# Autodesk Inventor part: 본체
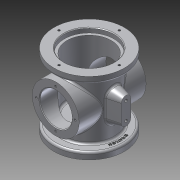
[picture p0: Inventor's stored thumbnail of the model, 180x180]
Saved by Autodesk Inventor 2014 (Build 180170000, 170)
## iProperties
Created: 2018-02
Part Number: 본체
Material: 알루미늄 6061
Document SubType Name: Modeling
Designer: OA65
Density: 2.71 g/cm^3
Appearance: 알루미늄 - 평지
Mass: 771.847 g
Surface Area: 821.675 cm^2
Volume: 284.814 cm^3
Author: OA65
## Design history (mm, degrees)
sketch "스케치1"
  geometry: C1 r 33 at (0, 0); C2 r 38 at (0, 0); 1 further point
  constraints: 2 centre point, 2 coincident
  dimensions: "d0" = 66 diameter of C1; "d1" = 76 diameter of C2
extrude "돌출1" new body sketch "스케치1" distance "d2" = 108; taper "d3" = 0 deg
sketch "스케치2"
  geometry: C1 r 38 at (0, 0) reference; C2 r 52.5 at (0, 0)
  constraints: 1 centre point, 1 coincident
  dimensions: "d4" = 105 diameter of C2
extrude "돌출2" join sketch "스케치2" distance "d5" = 10; taper "d6" = 0 deg
sketch "스케치3"
  geometry: C1 r 38 at (0, 0) reference; C2 r 52.5 at (0, 0)
  constraints: 1 centre point, 1 coincident
  dimensions: "d8" = 105 diameter of C2
extrude "돌출3" join sketch "스케치3" distance "d9" = 10; taper "d10" = 0 deg
sketch "스케치4"
  geometry: C1 r 52.5 at (0, 0) reference; C2 r 37 at (0, 0)
  constraints: 1 centre point, 1 coincident
  dimensions: "d11" = 74 diameter of C2
extrude "돌출4" cut sketch "스케치4" distance "d12" = 7; taper "d13" = 0 deg
sketch "스케치5"
  geometry: C1 r 37 at (0, 0) reference; C2 r 33 at (0, 0)
  constraints: 1 centre point, 1 coincident
  dimensions: "d14" = 66 diameter of C2
extrude "돌출5" cut sketch "스케치5" distance "d15" = 79; taper "d16" = 0 deg
sketch "스케치6"
  geometry: C1 r 52.5 at (0, 0) reference; C2 r 34 at (0, 0)
  constraints: 1 centre point, 1 coincident
  dimensions: "d17" = 68 diameter of C2
extrude "돌출6" cut sketch "스케치6" distance "d18" = 16; taper "d19" = 0 deg
sketch "스케치7"
  geometry: L1 (38, 10)-(52.5, 10) reference; L2 (52.5, 10)-(52.5, 0) reference; L3 (52.5, 0)-(37, 0) reference; L4 (37, 0)-(37, 7) reference; L5 (37, 7)-(33, 7) reference; L6 (33, 7)-(33, 86) reference; L7 (33, 86)-(-33, 86) reference; L8 (-33, 86)-(-33, 7) reference; L9 (-33, 7)-(-37, 7) reference; L10 (-37, 7)-(-37, 0) reference; L11 (-37, 0)-(-52.5, 0) reference; L12 (-52.5, 0)-(-52.5, 10) reference; L13 (-52.5, 10)-(-38, 10) reference; L14 (-38, 10)-(-38, 98) reference; L15 (-38, 98)-(-52.5, 98) reference; L16 (-52.5, 98)-(-52.5, 108) reference; L17 (-52.5, 108)-(-34, 108) reference; L18 (-34, 108)-(-34, 92) reference; L19 (-34, 92)-(34, 92) reference; L20 (34, 92)-(34, 108) reference; L21 (34, 108)-(52.5, 108) reference; L22 (52.5, 108)-(52.5, 98) reference; L23 (52.5, 98)-(38, 98) reference; L24 (38, 98)-(38, 10) reference; L25 (0, 108)-(0, 54); C1 r 24 at (0, 54); C2 r 35 at (0, 54); 1 further point
  constraints: 2 centre point, 2 coincident, 2 end point, 1 parallel
  dimensions: "d20" = 54 distance of L25.start L25.end; "d21" = 48 diameter of C1; "d22" = 70 diameter of C2
extrude "돌출7" join sketch "스케치7" stored distance "d23" = 100; taper "d24" = 0 deg
sketch "스케치8"
  geometry: C1 r 24 at (0, 0) reference; C2 r 35 at (0, 0) reference; C3 r 24 at (0, 0); 1 further point
  constraints: 1 centre point, 1 coincident, 1 concentric
extrude "돌출8" cut sketch "스케치8" distance "d25" = 150; taper "d26" = 0 deg
sketch "스케치9"
  geometry: C1 r 37 at (0, 0) reference; C2 r 52.5 at (0, 0) reference; C3 r 37 at (0, 0)
  constraints: 1 centre point, 1 coincident, 1 concentric
extrude "돌출9" cut sketch "스케치9" distance "d27" = 86; taper "d28" = 0 deg
sketch "스케치10"
  geometry: C1 r 37 at (0, 0) reference; C2 r 33 at (0, 0)
  constraints: 1 centre point, 1 coincident
  dimensions: "d29" = 66 diameter of C2
extrude "돌출10" join sketch "스케치10" distance "d30" = 79; taper "d31" = 0 deg
sketch "스케치11"
  geometry: C1 r 24 at (0, 0) reference; C2 r 35 at (0, 0) reference; C3 r 24 at (0, 0); 1 further point
  constraints: 1 centre point, 1 coincident, 1 concentric
extrude "돌출11" cut sketch "스케치11" distance "d32" = 150; taper "d33" = 0 deg
sketch "스케치12"
  geometry: C1 r 33 at (0, 0) reference; C2 r 5 at (0, 0)
  constraints: 1 centre point, 1 coincident
  dimensions: "d34" = 10 diameter of C2
extrude "돌출12" cut sketch "스케치12" distance "d35" = 14; taper "d36" = 0 deg
node "작업 평면1"
fillet "모깎기1" dims "d50" = 3
fillet "모깎기2" dims "d51" = 3
chamfer "모따기1" distance "d52" = 1; stored, may be unused: second distance "d53" = 2, angle "d54" = 45 deg
sketch "스케치17" dims "d64" = 90
  geometry: C1 r 38 at (0, 0) reference; 2 further points
  constraints: 1 coincident, 1 vertical alignment, 2 other
hole "구멍2" sketch "스케치17" at (0, 45) diameter "d65" = 3.242; stored, may be unused: countersink angle "d69" = 90 deg, drill point angle "d71" = 118 deg; dims "d66" = 4, "d67" = 4, "d68" = 2, "d70" = 6
sketch "스케치18" dims "d75" = 58
  geometry: C1 r 25 at (0, 0) reference; 3 further points
  constraints: 1 coincident, 1 vertical alignment, 2 other
hole "구멍3" sketch "스케치18" at (0, 29) diameter "d76" = 3.242; stored, may be unused: countersink angle "d80" = 90 deg, drill point angle "d82" = 118 deg; dims "d77" = 4, "d78" = 4, "d79" = 2, "d81" = 6
node "작업 평면2"
sketch "스케치19"
  geometry: L1 (-31, 92)-(-5, 92) reference; L2 (-5, 92)-(-5, 86) reference; L3 (-5, 86)-(-30, 86) reference; L4 (-33, 83)-(-33, 7) reference; L5 (-33, 7)-(-37, 7) reference; L6 (-37, 7)-(-37, 1) reference; L7 (-37, 1)-(-38, 0) reference; L8 (-38, 0)-(-43.379, 0) reference; L9 (-43.379, 0)-(-43.379, 6) reference; L10 (-43.379, 6)-(-45, 6.974) reference; L11 (-45, 6.974)-(-46.621, 6) reference; L12 (-46.621, 6)-(-46.621, 0) reference; L13 (-46.621, 0)-(-52.5, 0) reference; L14 (-52.5, 0)-(-52.5, 7) reference; L15 (-49.5, 10)-(-41, 10) reference; L16 (-38, 13)-(-38, 95) reference; L17 (-41, 98)-(-49.5, 98) reference; L18 (-52.5, 101)-(-52.5, 108) reference; L19 (-52.5, 108)-(-34, 108) reference; L20 (-34, 108)-(-34, 95) reference; L21 (34, 95)-(34, 108) reference; L22 (34, 108)-(52.5, 108) reference; L23 (52.5, 108)-(52.5, 101) reference; L24 (49.5, 98)-(41, 98) reference; L25 (38, 95)-(38, 13) reference; L26 (41, 10)-(49.5, 10) reference; L27 (52.5, 7)-(52.5, 0) reference; L28 (52.5, 0)-(46.621, 0) reference; L29 (46.621, 0)-(46.621, 6) reference; L30 (46.621, 6)-(45, 6.974) reference; L31 (45, 6.974)-(43.379, 6) reference; L32 (43.379, 6)-(43.379, 0) reference; L33 (43.379, 0)-(38, 0) reference; L34 (38, 0)-(37, 1) reference; L35 (37, 1)-(37, 7) reference; L36 (37, 7)-(33, 7) reference; L37 (33, 7)-(33, 83) reference; L38 (30, 86)-(5, 86) reference; L39 (5, 86)-(5, 92) reference; L40 (5, 92)-(31, 92) reference; L41 (0, 54)-(55, 54); L42 (55, 41)-(55, 34); L43 (55, 34)-(38, 29.445); L44 (55, 67)-(55, 74); L45 (55, 74)-(38, 78.555); L46 (55, 41)-(38, 41); L47 (55, 67)-(38, 67); A1 r 3 centre (-31, 95) between (-34, 95) and (-31, 92) reference; A2 r 3 centre (-30, 83) between (-30, 86) and (-33, 83) reference; A3 r 3 centre (-49.5, 7) between (-49.5, 10) and (-52.5, 7) reference; A4 r 3 centre (-41, 13) between (-41, 10) and (-38, 13) reference; A5 r 3 centre (-41, 95) between (-38, 95) and (-41, 98) reference; A6 r 3 centre (-49.5, 101) between (-52.5, 101) and (-49.5, 98) reference; A7 r 3 centre (31, 95) between (31, 92) and (34, 95) reference; A8 r 3 centre (49.5, 101) between (49.5, 98) and (52.5, 101) reference; A9 r 3 centre (41, 95) between (41, 98) and (38, 95) reference; A10 r 3 centre (41, 13) between (38, 13) and (41, 10) reference; A11 r 3 centre (49.5, 7) between (52.5, 7) and (49.5, 10) reference; A12 r 3 centre (30, 83) between (33, 83) and (30, 86) reference; 2 further points
  constraints: 14 end point, 4 point on line, 3 perpendicular, 1 collinear, 1 parallel, 1 other
  dimensions: "d87" = 55 distance of L41.start L41.end; "d88" = 20 distance of L41.end L42.end; "d89" = 20 distance of L41.end L44.end; "d90" = 13 distance of L42.start L41.end; "d91" = 13 distance of L44.start L41.end
  node "절단 모서리 투영4"
revolve "회전3" stored, may be unused: angle "d92" = 90 deg
revolve "회전4" stored, may be unused: angle "d93" = 90 deg
sketch "스케치20"
  geometry: L1 (-7, 0)-(-7, -26); L2 (7, 0)-(7, -26); A1 r 7 centre (0, 0) between (-7, 0) and (7, 0) reference; A2 r 7 centre (0, -26) between (-7, -26) and (7, -26) reference; A3 r 7 centre (0, 0) between (-7, 0) and (7, 0) reference; 1 further point
  constraints: 6 point on circle, 4 end point, 4 tangent
extrude "돌출15" join sketch "스케치20" stored distance "d94" = 15; taper "d95" = 15 deg
fillet "모깎기3" dims "d96" = 3
sketch "스케치21"
  geometry: A1 r 7 centre (-7, 0) between (-14, 0) and (0, 0) reference; A2 r 7 centre (-7, 26) between (0, 26) and (-14, 26) reference; 3 further points
  constraints: 2 coincident
hole "구멍4" sketch "스케치21" at (-7, 26), (-7, 0) diameter "d97" = 4.134; stored, may be unused: countersink angle "d101" = 90 deg, drill point angle "d103" = 118 deg; dims "d98" = 6, "d99" = 4, "d100" = 2, "d102" = 8
sketch "스케치22" dims "d104" = 86
  geometry: L1 (0, 0)-(0, 43); C1 r 41 at (0, 0) reference
  constraints: 2 end point, 1 coincident, 1 vertical, 1 vertical alignment, 2 other
feature "엠보싱1" sketch "스케치22" dims "d0" = 66, "d1" = 76, "d105" = 0.5, "d106" = 0
node "솔리드1"
pattern_circular "원형 패턴1" dims angle "d73" = 360 deg
pattern_circular "원형 패턴2" dims angle "d84" = 360 deg
mirror "대칭3"
node "절단 모서리 투영1"
node "절단 모서리 투영5"
other parameters: "d49" = 0, "d86" = 0
